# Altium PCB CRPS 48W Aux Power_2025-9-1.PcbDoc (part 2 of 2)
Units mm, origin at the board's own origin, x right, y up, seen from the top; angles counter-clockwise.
Board outline 50 x 33.8 mm, 6 copper layers (TopLayer, Layer2, Layer3, Layer4, Layer5, BottomLayer), stack 1.394 mm thick; 52 components, 33 nets, 144 pads, 115 vias.
Unrouted connection lines stored in the file: 30.
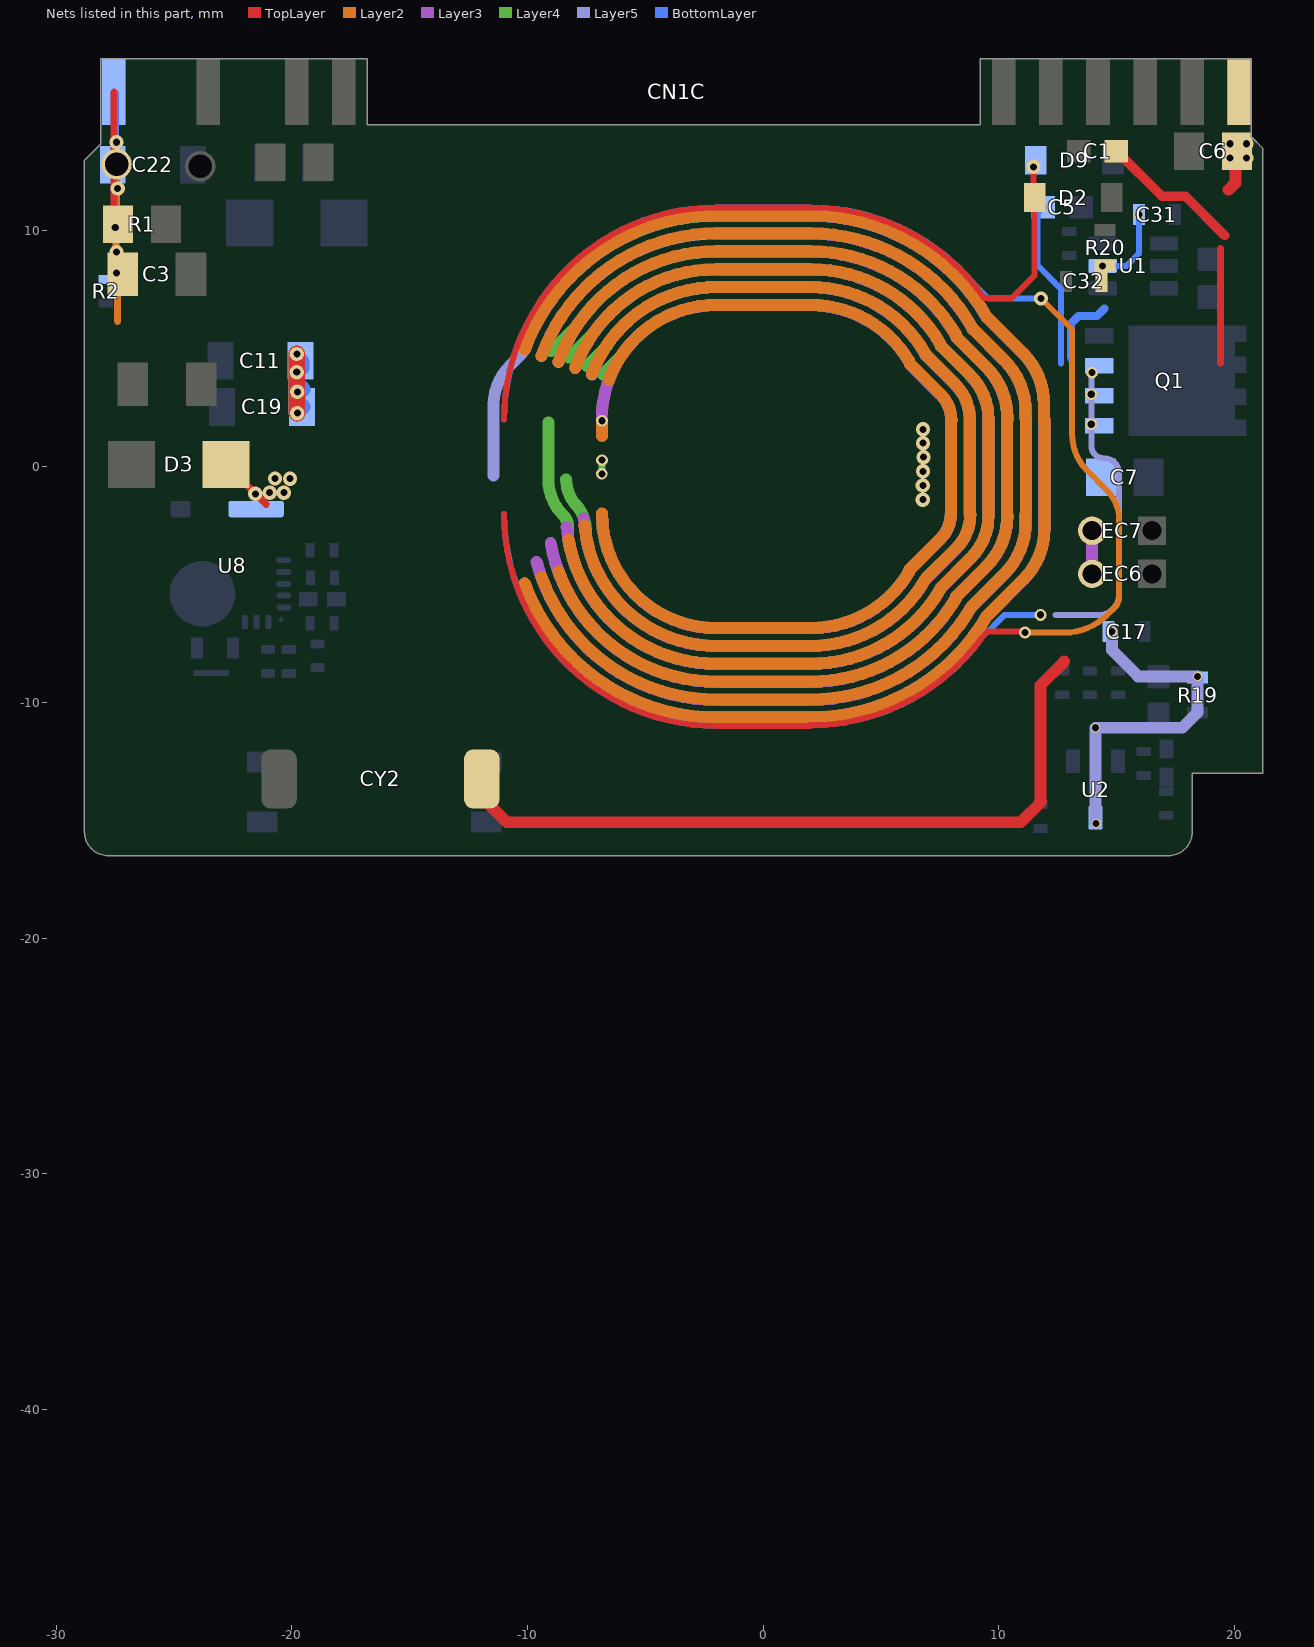
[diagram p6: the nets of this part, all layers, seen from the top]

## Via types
v1: diameter 0.61, hole 0.3, TopLayer to BottomLayer, tented both sides, 71 vias
v2: diameter 0.4, hole 0.3, TopLayer to BottomLayer, tented both sides, 19 vias
v3: diameter 0.5, hole 0.2, TopLayer to BottomLayer, tented both sides, 12 vias
v4: diameter 0.5, hole 0.3, Layer2 to Layer5, tented both sides, 8 vias
v5: diameter 0.508, hole 0.305, TopLayer to BottomLayer, 5 vias

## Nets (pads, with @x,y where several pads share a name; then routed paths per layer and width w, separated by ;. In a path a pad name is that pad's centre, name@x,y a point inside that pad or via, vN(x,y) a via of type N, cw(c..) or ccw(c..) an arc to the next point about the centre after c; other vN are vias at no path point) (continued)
SGND: C1.2 C6.2 C7.2 C17.1 CN1C.19 CN1C.20 CY2.1 EC6.2 EC7.2 R19.1 U2.3 | length 1205.6
  TopLayer w0.25: v1(20.5,13.096) v1(20.5,13.7)
  TopLayer w0.3: 19.396,4.395 19.396,9.246
  TopLayer w0.4: C1.2@14.984,13.377 15.009,13.377 16.914,11.472 17.91,11.472 19.572,9.809
  TopLayer w0.5: CY2.1@-11.942,-13.25 -12.261,-13.569 -12.261,-13.708 -10.881,-15.088 10.927,-15.088 11.762,-14.253 11.762,-9.274 12.764,-8.271
  TopLayer w0.505: 19.74,11.748 20.036,12.044 20.036,12.824 19.793,13.068 v1(19.793,13.096)
  Layer3 w0.5: 8.758,2.042 ccw(c8.786,2.042) 8.766,2.023
  Layer3 w0.505: -10.122,-4.958 ccw(c-1.996,-2) -1.996,-10.648 2.004,-10.648 ccw(c2.004,-2) 9.494,-6.324 ; -9.616,-4.042 ccw(c-1.996,-2) -1.996,-9.889 2.004,-9.889 ccw(c2.004,-2) 8.836,-5.944 ; -9.017,-3.238 ccw(c-1.996,-2) -1.996,-9.13 2.004,-9.13 ccw(c2.004,-2) 8.179,-5.565 ; -8.342,-2.555 ccw(c-1.996,-2) -1.996,-8.37 ; -7.603,-2.196 ccw(c-1.996,-2) -1.996,-7.611 ; -6.844,-2.004 ccw(c-1.996,-2.004) -1.996,-6.853 2.004,-6.853 ccw(c2.004,-2) 6.207,-4.426 ; -1.996,-8.371 2.004,-8.371 ; -1.996,-7.612 2.004,-7.612 ; -1.996,6.853 2.004,6.853 cw(c2.004,2) 6.207,4.427 ; -1.996,7.612 2.004,7.612 ; -1.996,8.371 2.004,8.371 ; -1.996,9.13 2.004,9.13 cw(c2.004,2) 8.179,5.565 ; -1.996,9.889 2.004,9.889 cw(c2.004,2) 8.836,5.945 ; -1.996,10.648 2.004,10.648 cw(c2.004,2) 9.494,6.324 ; 2.004,-8.37 ccw(c2.004,-2) 7.521,-5.185 ; 2.004,-7.611 ccw(c2.004,-2) 6.864,-4.805 ; 2.004,7.611 cw(c2.004,2) 6.864,4.806 ; 2.004,8.37 cw(c2.004,2) 7.521,5.185 ; 6.204,-4.375 7.53,-3.049 ccw(c6.506,-2.025) 7.954,-2.025 ; 6.229,4.35 7.52,3.06 cw(c6.41,1.95) 7.979,1.95 ; 6.879,-4.775 8.196,-3.458 ccw(c6.788,-2.05) 8.779,-2.05 ; 6.904,4.725 8.153,3.476 cw(c6.702,2.025) 8.754,2.025 ; 7.529,-5.15 8.812,-3.867 ccw(c7.019,-2.075) 9.554,-2.075 ; 7.529,5.125 8.776,3.878 cw(c6.899,2) 9.554,2 ; 7.969,-1.997 7.969,2.003 ; 8.179,-5.525 9.456,-4.248 ccw(c7.288,-2.08) 10.354,-2.08 10.354,-2.075 ; 8.204,5.475 9.456,4.223 cw(c7.288,2.055) 10.354,2.055 10.354,1.975 ; 8.761,-1.997 8.761,2.003 ; 8.854,-5.925 10.231,-4.548 ccw(c8.063,-2.38) 11.129,-2.38 11.129,-2.025 ; 8.879,5.85 10.231,4.498 cw(c8.063,2.33) 11.129,2.33 11.129,2.075 ; 9.525,6.299 11.006,4.818 cw(c8.838,2.65) 11.904,2.65 11.904,1.975 ; 9.529,-6.3 11.031,-4.798 ccw(c8.863,-2.63) 11.929,-2.63 11.929,2.003 ; 9.553,-1.997 9.553,2.003 ; 10.345,-1.997 10.345,2.003 ; 11.137,-1.997 11.137,2.003 ; EC6.2@13.95,-4.709 EC6.2@13.95,-4.548 EC7.2@13.95,-2.715 EC7.2@14.138,-2.715 ; v1@19.793,13.068 v1(19.793,13.7)
  Layer4 w0.3: v4(-6.849,-0.304) v4(-6.844,0.275)
  Layer4 w0.5: 8.754,2.042 ccw(c8.781,2.042) 8.762,2.023
  Layer4 w0.505: -10.126,-4.958 ccw(c-2,-2) -2,-10.648 2,-10.648 ccw(c2,-2) 9.489,-6.324 ; -9.12,1.868 -9.12,-0.543 ccw(c-6.989,-0.543) -8.496,-2.05 cw(c-9.034,-2.588) -8.273,-2.588 -8.273,-3.106 ccw(c-2,-2) -2,-8.37 ; -9.002,4.898 -7.85,6.05 ; -8.947,-3.604 ccw(c-2,-2) -2,-9.13 2,-9.13 ccw(c2,-2) 8.175,-5.565 ; -8.625,7.559 cw(c-2,2) -2,10.648 2,10.648 cw(c2,2) 9.489,6.324 ; -8.364,-0.531 ccw(c-6.727,-0.531) -7.993,-1.568 ccw(c-6.727,-0.531) -7.901,-1.672 cw(c-8.264,-2.023) -7.867,-1.71 cw(c-9.12,-2.696) -7.526,-2.696 -7.526,-2.974 ccw(c-2,-2) -2,-7.611 ; -8.252,4.623 -7.25,5.625 ; -7.841,6.09 cw(c-2,2) -2,9.13 2,9.13 cw(c2,2) 8.175,5.565 ; -7.477,4.273 -6.66,5.09 ccw(c-6.746,5.175) -6.625,5.175 ; -7.218,5.654 cw(c-2,2) -2,8.37 ; -6.853,-2 ccw(c-2,-2) -2,-6.853 2,-6.853 ccw(c2,-2) 6.203,-4.426 ; -6.812,3.913 -6.025,4.7 ; -6.596,5.218 cw(c-2,2) -2,7.611 ; -5.975,4.784 cw(c-2,2) -2,6.853 2,6.853 cw(c2,2) 6.203,4.427 ; -2,-8.371 2,-8.371 ; -2,-7.612 2,-7.612 ; -2,7.612 2,7.612 ; -2,8.371 2,8.371 ; 2,-8.37 ccw(c2,-2) 7.517,-5.185 ; 2,-7.611 ccw(c2,-2) 6.859,-4.805 ; 2,7.611 cw(c2,2) 6.859,4.806 ; 2,8.37 cw(c2,2) 7.517,5.185 ; 6.2,-4.375 7.526,-3.049 ccw(c6.501,-2.025) 7.95,-2.025 ; 6.225,4.35 7.515,3.06 cw(c6.406,1.95) 7.975,1.95 ; 6.875,-4.775 8.192,-3.458 ccw(c6.783,-2.05) 8.775,-2.05 ; 6.9,4.725 8.149,3.476 cw(c6.698,2.025) 8.75,2.025 ; 7.525,-5.15 8.808,-3.867 ccw(c7.015,-2.075) 9.55,-2.075 ; 7.525,5.125 8.772,3.878 cw(c6.894,2) 9.55,2 ; 7.965,-1.997 7.965,2.003 ; 8.175,-5.525 9.452,-4.248 ccw(c7.284,-2.08) 10.35,-2.08 10.35,-2.075 ; 8.2,5.475 9.452,4.223 cw(c7.284,2.055) 10.35,2.055 10.35,1.975 ; 8.757,-1.997 8.757,2.003 ; 9.52,6.299 11.002,4.818 cw(c8.834,2.65) 11.9,2.65 11.9,1.975 ; 9.525,-6.3 11.027,-4.798 ccw(c8.859,-2.63) 11.925,-2.63 11.925,2.003 ; 9.549,-1.997 9.549,2.003 ; 10.341,-1.997 10.341,2.003
  Layer2 w0.5: 8.763,2.056 ccw(c8.79,2.056) 8.771,2.037
  Layer2 w0.505: -10.118,-4.944 ccw(c-1.991,-1.986) -1.991,-10.634 2.009,-10.634 ccw(c2.009,-1.986) 9.498,-6.31 ; -10.118,4.972 cw(c-1.991,2.014) -1.991,10.662 2.009,10.662 cw(c2.009,2.014) 9.498,6.338 ; -9.405,-4.684 ccw(c-1.991,-1.986) -1.991,-9.875 2.009,-9.875 ccw(c2.009,-1.986) 8.841,-5.931 ; -9.405,4.712 cw(c-1.991,2.014) -1.991,9.903 2.009,9.903 cw(c2.009,2.014) 8.841,5.958 ; -8.691,-4.425 ccw(c-1.991,-1.986) -1.991,-9.116 2.009,-9.116 ccw(c2.009,-1.986) 8.183,-5.551 ; -8.691,4.452 cw(c-1.991,2.014) -1.991,9.144 2.009,9.144 cw(c2.009,2.014) 8.183,5.579 ; -8.265,-3.092 ccw(c-1.991,-1.986) -1.991,-8.356 ; -7.977,4.192 cw(c-1.991,2.014) -1.991,8.384 ; -7.581,-2.475 ccw(c-1.991,-1.986) -1.991,-7.597 2.009,-7.598 ccw(c2.009,-1.986) 6.868,-4.792 ; -7.264,3.933 cw(c-1.991,2.014) -1.991,7.625 ; -6.844,-1.986 ccw(c-1.991,-1.986) -1.991,-6.839 2.009,-6.839 ccw(c2.009,-1.986) 6.211,-4.413 ; -6.844,1.29 v4(-6.844,1.95) ; -6.552,3.674 cw(c-1.991,2.014) -1.991,6.867 2.009,6.867 cw(c2.009,2.014) 6.211,4.44 ; -1.991,-8.357 2.009,-8.357 ; -1.991,7.626 2.009,7.626 ; -1.991,8.385 2.009,8.385 ; 2.009,-8.356 ccw(c2.009,-1.986) 7.525,-5.171 ; 2.009,7.625 cw(c2.009,2.014) 6.868,4.819 ; 2.009,8.384 cw(c2.009,2.014) 7.525,5.199 ; 6.209,-4.361 7.534,-3.035 ccw(c6.51,-2.011) 7.959,-2.011 ; 6.234,4.364 7.524,3.073 cw(c6.414,1.964) 7.984,1.964 ; 6.884,-4.761 8.2,-3.445 ccw(c6.792,-2.036) 8.784,-2.036 ; 6.909,4.739 8.158,3.49 cw(c6.707,2.039) 8.759,2.039 ; 7.534,-5.136 8.816,-3.854 ccw(c7.024,-2.061) 9.559,-2.061 ; 7.534,5.139 8.781,3.892 cw(c6.903,2.014) 9.559,2.014 ; 7.974,-1.983 7.974,2.017 ; 8.184,-5.511 9.461,-4.234 ccw(c7.293,-2.066) 10.359,-2.066 10.359,-2.061 ; 8.209,5.489 9.461,4.237 cw(c7.293,2.069) 10.359,2.069 10.359,1.989 ; 8.766,-1.983 8.766,2.017 ; 8.859,-5.911 10.236,-4.534 ccw(c8.068,-2.366) 11.134,-2.366 11.134,-2.011 ; 8.884,5.864 10.236,4.512 cw(c8.068,2.344) 11.134,2.344 11.134,2.089 ; 9.529,6.313 11.011,4.832 cw(c8.843,2.664) 11.909,2.664 11.909,1.989 ; 9.534,-6.286 11.036,-4.784 ccw(c8.868,-2.616) 11.934,-2.616 11.934,2.017 ; 9.558,-1.983 9.558,2.017 ; 10.35,-1.983 10.35,2.017 ; 11.142,-1.983 11.142,2.017
  Layer5 w0.5: 8.763,2.042 ccw(c8.79,2.042) 8.771,2.023
  Layer5 w0.505: -11.445,-0.378 -11.445,0.203 -11.445,2.461 ccw(c-12.197,2.461) -11.45,2.553 cw(c-10.949,2.612) -11.454,2.625 cw(c-8.915,2.535) -10.711,4.331 -10.224,4.818 ; -10.118,-4.958 ccw(c-1.991,-2) -1.991,-10.648 2.009,-10.648 ccw(c2.009,-2) 9.498,-6.324 ; -10.118,4.958 cw(c-1.991,2) -1.991,10.648 2.009,10.648 cw(c2.009,2) 9.498,6.324 ; -9.405,-4.698 ccw(c-1.991,-2) -1.991,-9.889 2.009,-9.889 ccw(c2.009,-2) 8.841,-5.945 ; -9.405,4.698 cw(c-1.991,2) -1.991,9.889 2.009,9.889 cw(c2.009,2) 8.841,5.944 ; -8.81,-4.085 ccw(c-1.991,-2) -1.991,-9.13 2.009,-9.13 ccw(c2.009,-2) 8.183,-5.565 ; -8.691,4.439 cw(c-1.991,2) -1.991,9.13 2.009,9.13 cw(c2.009,2) 8.183,5.565 ; -8.265,-3.106 ccw(c-1.991,-2) -1.991,-8.37 ; -7.977,4.179 cw(c-1.991,2) -1.991,8.37 ; -7.581,-2.489 ccw(c-1.991,-2) -1.991,-7.611 ; -7.264,3.919 cw(c-1.991,2) -1.991,7.611 ; -6.844,-2 ccw(c-1.991,-2) -1.991,-6.853 2.009,-6.853 ccw(c2.009,-2) 6.211,-4.427 ; -6.552,3.66 cw(c-1.991,2) -1.991,6.853 2.009,6.853 cw(c2.009,2) 6.211,4.426 ; -1.991,-8.371 2.009,-8.371 ; -1.991,-7.612 2.009,-7.612 ; -1.991,7.612 2.009,7.612 ; -1.991,8.371 2.009,8.371 ; 2.009,-8.37 ccw(c2.009,-2) 7.525,-5.185 ; 2.009,-7.611 ccw(c2.009,-2) 6.868,-4.806 ; 2.009,7.611 cw(c2.009,2) 6.868,4.805 ; 2.009,8.37 cw(c2.009,2) 7.525,5.185 ; 6.209,-4.375 7.534,-3.049 ccw(c6.51,-2.025) 7.959,-2.025 ; 6.234,4.35 7.524,3.06 cw(c6.414,1.95) 7.984,1.95 ; 6.884,-4.775 8.2,-3.458 ccw(c6.792,-2.05) 8.784,-2.05 ; 6.909,4.725 8.158,3.476 ; 7.534,-5.15 8.816,-3.868 ccw(c7.024,-2.075) 9.559,-2.075 ; 7.534,5.125 8.781,3.878 cw(c6.903,2) 9.559,2 ; 7.974,-1.997 7.974,2.003 ; 8.158,3.476 cw(c6.706,2.025) 8.759,2.025 ; 8.184,-5.525 9.461,-4.248 ccw(c7.293,-2.08) 10.359,-2.08 10.359,-2.075 ; 8.209,5.475 9.461,4.223 cw(c7.293,2.055) 10.359,2.055 10.359,1.975 ; 8.766,-1.997 8.766,2.003 ; 8.859,-5.925 10.236,-4.548 ccw(c8.068,-2.38) 11.134,-2.38 11.134,-2.025 ; 8.884,5.85 10.236,4.498 cw(c8.068,2.33) 11.134,2.33 11.134,2.075 ; 9.529,6.299 11.011,4.818 cw(c8.843,2.65) 11.909,2.65 11.909,1.975 ; 9.534,-6.3 11.036,-4.798 ccw(c8.868,-2.63) 11.934,-2.63 11.934,2.003 ; 9.558,-1.997 9.558,2.003 ; 10.35,-1.997 10.35,2.003 ; 11.142,-1.997 11.142,2.003 ; v2(14.12,-15.139) 14.096,-15.115 v2(14.096,-11.075) 17.779,-11.075 18.428,-10.426 v2(18.428,-8.894) 15.904,-8.894 14.8,-7.79 v2(14.8,-7)
Vaux: D2.2 D9.2 | length 139.7
  TopLayer w0.25: v1(11.462,12.721) 11.462,11.472 D2.2@11.517,11.417
  TopLayer w0.254: -11,-2 ccw(c-2,-2) -2,-11 2,-11 ; -11,2 cw(c-2,2) -2,11 2,11 cw(c2,2) 9.372,7.162 10.558,7.162 11.517,8.121 D2.2@11.517,11.417 ; 2,-10.969 ccw(c2,-2) 9.26,-7.267 9.532,-6.995 11.057,-6.995 v5(11.1,-7.038)
  Layer2 w0.254: v5(11.1,-7.038) 12.783,-7.038 ccw(c12.783,-4.498) 14.579,-6.294 14.913,-5.96 ccw(c14.461,-5.508) 15.1,-5.508 15.1,-2.258 ccw(c13.321,-2.258) 14.579,-1 13.735,-0.156 cw(c15.27,1.378) 13.1,1.378 13.1,5.823 v1(11.786,7.137)
  BottomLayer w0.254: -10.996,-2 ccw(c-1.996,-2) -1.996,-11 2.004,-11 ; -10.996,2 cw(c-1.996,2) -1.996,11 2.004,11 cw(c2.004,2) 8.899,7.785 9.546,7.137 v1(11.786,7.137) ; 2.004,-10.969 ccw(c2.004,-2) 9.264,-7.267 ; 9.26,-7.267 10.244,-6.283 v5(11.762,-6.283)
Vbus: C3.2 C11.1 C19.1 C22.1 CN1C.2 pad.12@-27.439,12.833 R1.2 R2.2 | length 34.1
  TopLayer w0.305: pad.12@-27.55,12.75 v1@-27.55,11.8 ; -27.55,15.9 -27.55,13.763 -27.55,12.944 pad.12@-27.439,12.833 v1(-27.439,12.75) ; v1(-27.495,10.144) -27.495,10.232 -27.55,10.287 v1@-27.55,11.8 ; v1@-27.55,11.8 v1(-27.393,11.8) ; v1@-27.55,11.8 v1(-27.393,11.8) ; v1@-27.55,11.8 v1(-27.393,11.8) ; v1@-27.55,11.8 v1(-27.393,11.8) ; v1@-27.55,11.8 v1(-27.393,11.8) ; v1@-27.55,11.8 v1(-27.393,11.8) ; v1@-27.55,11.8 v1(-27.393,11.8) ; v1@-27.55,11.8 v1(-27.393,11.8)
  TopLayer w0.7: v1(-19.786,4.781) -19.786,2.284 v1(-19.77,2.269)
  Layer3 w0.505: -6.853,2 cw(c-2,2) -2,6.853
  Layer4 w0.7: v1(-19.786,4.781) -19.786,2.284 v1(-19.77,2.269)
  Layer2 w0.305: v1(-27.439,12.75) -27.439,11.8 -27.439,10.199 v1(-27.495,10.144) -27.467,10.116 -27.467,9.129 -27.444,9.105 -27.444,8.221 v1(-27.448,8.217) -27.402,8.17 -27.402,6.171
  Layer5 w0.7: v1(-19.786,4.781) -19.786,2.284 v1(-19.77,2.269)
  BottomLayer w0.305: CN1C.2@-27.55,15.9 -27.495,15.845 C22.1@-27.495,12.813
  BottomLayer w0.7: v1(-19.77,3.175) -19.77,3.096 -19.767,3.092 -19.767,2.735 C19.1@-19.567,2.535 ; C11.1@-19.636,4.496 -19.601,4.461 -19.601,4.204 v1(-19.793,4.013) -19.793,3.517 C19.1@-19.567,3.292
  other v1: -27.439,9.11 -27.439,13.763
VSR_SW: C5.2 C31.2 C32.2 Q1.1 Q1.2 Q1.3 R20.1 U1.2 | length 27.8
  TopLayer w0.254: C32.2@14.358,7.861 14.358,8.477 v2(14.4,8.52)
  Layer5 w0.254: 12.4,-6.3 14.216,-6.3 ccw(c14.216,-5.416) 15.1,-5.416 15.1,-0.292 ccw(c14.453,-0.292) 14.453,0.356 cw(c14.453,0.893) 13.916,0.893 v5(13.916,1.8) 13.933,1.817 v5@13.933,3.12 ; v5@13.916,3.102 v5@13.933,3.12 ; v5(13.95,4) 13.933,3.982 v5@13.933,3.12
  BottomLayer w0.25: Q1.1@13.887,1.771 v5(13.916,1.8)
  BottomLayer w0.254: C5.2@11.885,11 11.633,10.748 11.633,8.539 12.624,7.549 12.624,4.379 ; 13.056,4.518 13.056,4.648 ; v2(14.4,8.52) 15.413,8.52 15.938,9.044 v2(15.938,10.69)
  BottomLayer w0.35: 13.056,4.648 13.056,6.068 13.376,6.389 14.157,6.389 14.478,6.71
  other v1: 6.772,-1.4 6.772,-0.8 6.776,-0.2 6.799,0.406 6.776,1 6.776,1.581
  other v5: 13.916,3.073
VSW: D3.2 U8.2 | length 2.4
  TopLayer w0.305: D3.2@-22.8,0.1 -21.103,-1.597
  other v1: -21.55,-1.15 -20.944,-1.1 -20.339,-1.1 -20.716,-0.5 -20.079,-0.508
pads on no net: CN1C.1 CN1C.5 CN1C.6 CN1C.7 CN1C.8 CN1C.10 CN1C.11 CN1C.12 CN1C.13 CN1C.14 CN1C.15 CN1C.16 CN1C.18
copper on no net: | length 361.6
  TopLayer w0.254: -11,-2 -11,2
  TopLayer w0.305: 10.092,14.976 10.092,15.792 10.2,15.9 10.2,15.161 ; 17.85,15.434 17.97,15.554 18.2,15.9 ; 20.12,15.07 20.12,15.58 20.07,15.63 19.93,15.63 20.2,15.9 20.3,15.8 20.3,15.25
  Layer3 w0.5: -19.77,-0.722 -19.137,-0.722 ccw(c-19.137,0.432) -17.983,0.432 -17.983,1.219 cw(c-16.713,1.219) -16.713,2.489 ; -18.12,7.087 -18.12,6.298 ccw(c-18.086,6.298) -18.11,6.274 ccw(c-16.84,6.274) -16.84,5.004 -14.402,5.004 -13.722,5.004 cw(c-13.722,4.744) -13.538,4.928 cw(c-14.703,3.762) -13.056,3.762 v4(-13.056,1.4) ; -16.713,2.52 -15.128,2.52 -15.068,2.52 cw(c-15.068,1.651) -14.199,1.651 ccw(c-12.929,1.651) -12.929,0.381 -12.903,0.381 cw(c-12.903,-0.889) -11.633,-0.889 -11.633,-1.537 ; -11.633,-1.651 ccw(c-9.211,-1.651) -10.924,-3.364 -10.82,-3.467 cw(c-11.315,-3.962) -10.615,-3.962 ; -10.646,2.175 -10.646,-1.47 -10.646,-1.611 ccw(c-8.869,-1.611) -10.126,-2.868 cw(c-11.269,-4.011) -9.652,-4.011 ; -10.58,-4.011 -10.151,-4.934 ; -9.889,-0.859 -9.889,-1.172 ccw(c-8.429,-1.172) -9.461,-2.205 cw(c-10.457,-3.2) -9.049,-3.2 ; -9.889,-0.839 -9.889,2 ; -9.13,-0.722 -9.13,-0.204 -9.13,2 ; -9.105,-0.817 ccw(c-7.487,-0.817) -8.631,-1.961 cw(c-9.261,-2.591) -8.37,-2.591 ; -8.37,-0.445 -8.37,2 ; -8.338,-0.502 ccw(c-8.342,-0.506) -8.342,-0.5 ccw(c-6.957,-0.5) -7.936,-1.479 -7.878,-1.537 cw(c-8.523,-2.182) -7.611,-2.182 ; -7.625,-0.121 -7.625,1.966 cw(c-7.577,1.966) -7.611,2 ; -7.611,-0.204 ccw(c-6.426,-0.204) -7.264,-1.042 -7.176,-1.13 cw(c-7.939,-1.893) -6.86,-1.893
  Layer3 w0.505: -10.648,2 cw(c-2,2) -2,10.648 ; -9.889,2 cw(c-2,2) -2,9.889 ; -9.13,2 cw(c-2,2) -2,9.13 ; -8.37,2 cw(c-2,2) -2,8.37 ; -7.611,2 cw(c-2,2) -2,7.611 ; v4@-6.85,1.325 -6.85,2.175
  Layer4 w0.5: -19.66,8.575 -19.66,7.73 ccw(c-18.966,7.73) -19.456,7.239 cw(c-20.315,6.381) -19.101,6.381 -19.101,6.192 ; -19.101,6.092 ccw(c-19.099,6.092) -19.099,6.09 cw(c-19.099,6.091) -19.1,6.091 ; -19.1,6.141 ccw(c-18.076,6.141) -18.8,5.416 ccw(c-17.795,6.421) -17.795,5 -17.6,5 -11.6,5 ccw(c-11.6,6.005) -10.889,5.294 -8.625,7.559 ; -14.275,0.508 cw(c-13.232,1.55) -14.707,1.55 -14.707,2.068 cw(c-12.799,2.068) -14.148,3.418 -14.114,3.451 cw(c-12.573,1.91) -12.573,4.089 ; -14.251,0.484 -14.03,0.263 ccw(c-12.257,2.036) -12.257,-0.471 cw(c-12.257,-1.03) -11.862,-0.635 cw(c-12.494,-1.267) -11.6,-1.267 -11.6,-1.455 ; -13.818,1.067 cw(c-13.388,1.496) -13.995,1.496 -13.995,2.109 cw(c-12.955,2.109) -13.691,2.845 cw(c-12.336,1.491) -12.336,3.406 -11.19,3.569 ; -13.792,1.041 ccw(c-11.942,2.892) -11.942,0.275 -11.776,0.275 cw(c-11.776,-0.501) -11.228,0.048 -11.1,-0.08 cw(c-12.081,-1.061) -10.693,-1.061 -10.693,-1.455 ccw(c-8.836,-1.455) -10.149,-2.769 ; v4@-13.056,1.393 ccw(c-12.207,2.242) -12.207,1.041 -11.776,1.041 cw(c-11.776,-0.654) -10.578,0.545 cw(c-12.023,-0.9) -9.979,-0.9 ccw(c-8.023,-0.9) -9.406,-2.284 -9.277,-2.413 cw(c-9.941,-3.077) -9.002,-3.077 -9.002,-3.477 ; v4(-13.056,1.4) v4(-13.056,1.953) ; -12.522,4.089 -11.462,4.273 ccw(c-11.462,6.13) -10.149,4.817 ; v4@-12.197,2.33 v4(-12.197,1.939) ; v4(-12.197,2.461) v4(-12.197,1.939) ; -11.6,-1.513 ccw(c-9.285,-1.513) -10.922,-3.15 ; -11.151,3.569 ccw(c-11.151,5.607) -9.709,4.166 -9.593,4.283 ; -10.889,-3.175 -10.167,-4.899 ; -10.176,4.79 -10.149,4.817 ; -10.094,-2.828 cw(c-10.999,-3.734) -9.719,-3.734 -9.509,-4.407 ; -9.841,5.125 -10.149,4.817 ; -9.565,4.336 -9.002,4.898 ; -9.519,3.345 cw(c-10.848,4.674) -10.848,2.794 -11.339,2.794 ccw(c-11.339,1.58) -12.197,2.438 v4(-12.197,1.939) ; -9.509,3.366 -9.516,3.359 -9.351,3.524 -9.277,3.598 -8.252,4.623 ; -9.116,1.939 cw(c-7.438,1.939) -8.625,3.125 -7.477,4.273 ; -8.973,-3.541 cw(c-9.036,-3.604) -8.947,-3.604 ; -8.364,-0.531 ccw(c-8.372,-0.523) -8.36,-0.523 -8.36,2.134 cw(c-7.803,2.134) -8.197,2.528 -6.812,3.913 ; -7.29,1.4 -6.877,1.95 -6.883,1.956 ; -6.86,-1.893 cw(c-6.877,-1.91) -6.853,-1.91 -6.853,-2 ccw(c-7.685,-2) -7.097,-1.412 -7.352,-1.156 cw(c-6.727,-0.531) -7.611,-0.531 -7.611,0.1 -7.611,0.753 cw(c-7.022,0.753) -7.438,1.169 cw(c-7.147,0.878) -7.147,1.29 v4(-6.844,1.29) -6.844,1.95
  Layer4 w0.505: -9.752,5.223 -8.5,6.475 ; -9.503,-4.438 ccw(c-2,-2) -2,-9.889 2,-9.889 ccw(c2,-2) 8.832,-5.945 ; -8.462,6.525 cw(c-2,2) -2,9.889 2,9.889 cw(c2,2) 8.832,5.944 ; 8.85,-5.925 10.227,-4.548 ccw(c8.059,-2.38) 11.125,-2.38 ; 8.875,5.85 10.227,4.498 cw(c8.059,2.33) 11.125,2.33 ; 11.133,-2.38 11.133,2.203
  Layer2 w0.5: -18.974,3.378 -18.059,3.378 ; -18.194,3.378 -12.548,3.378 ccw(c-12.548,5.5) -11.047,4 -10.148,4.899 ; v4(-13.056,1.4) v4(-13.056,1.953) ; v4(-12.197,1.939) v4(-12.197,2.461) ; -10.151,-4.934 cw(c-9.42,-4.204) -10.453,-4.204 -10.453,2.394 cw(c-7.387,2.394) -9.555,4.562 -9.405,4.712 ; -9.405,-4.684 cw(c-8.646,-3.926) -9.719,-3.926 -9.719,2.409 cw(c-7.431,2.409) -9.049,4.026 -8.74,4.335 ccw(c-8.858,4.452) -8.691,4.452 ; -8.966,-3.752 -8.966,2.359 cw(c-7.227,2.359) -8.457,3.588 -8.001,4.115 ; -8.941,-3.81 -8.937,-3.817 -8.712,-4.318 ; -8.719,-4.361 -8.713,-4.368 ; -8.273,-3.106 -8.273,1.917 cw(c-5.91,1.917) -7.581,3.588 -7.283,3.886 ccw(c-7.33,3.933) -7.264,3.933 ; -7.585,-2.489 -7.585,1.924 cw(c-5.977,1.924) -7.114,3.061 -6.587,3.588 ccw(c-6.672,3.674) -6.552,3.674 ; -6.86,-1.893 ccw(c-6.882,-1.871) -6.851,-1.871 -6.851,0.2 ; -6.851,-0.293 -6.851,0.273 cw(c-6.844,0.273) -6.849,0.278 cw(c-6.834,0.278) -6.844,0.289 ; -6.847,-0.288 ccw(c-6.852,-0.283) -6.844,-0.283 -6.844,0.142 ; -6.844,-1.991 -6.844,-1.838 ; 6.772,-1.4 ccw(c6.742,-1.37) 6.785,-1.37
  Layer5 w0.254: 11.762,-6.283 11.779,-6.3 12.4,-6.3
  Layer5 w0.5: v4(-13.056,1.4) v4(-13.056,1.953) ; v4@-12.197,2.136 v4(-12.197,2.461) ; v4@-12.197,2.298 -12.197,-1.617 ccw(c-9.131,-1.617) -11.299,-3.785 -10.151,-4.934 ; -11.445,-0.378 -11.445,-1.307 ccw(c-8.379,-1.307) -10.547,-3.475 -10.475,-3.547 ccw(c-10.431,-3.504) -10.431,-3.565 ; -10.65,0.7 -10.65,-0.894 ccw(c-7.584,-0.894) -9.752,-3.062 -8.893,-3.922 cw(c-9.216,-4.245) -8.759,-4.245 ; -10.646,0.283 -10.646,2.031 ; -10.647,2.136 cw(c-7.837,2.136) -9.824,4.123 -9.459,4.57 -9.449,4.572 ; -10.402,-3.594 -9.475,-4.521 ; -10.175,-4.91 -10.126,-4.958 ; -9.48,-4.516 cw(c-9.662,-4.698) -9.405,-4.698 ; -9.12,0.285 -9.12,2.036 ; -9.12,0.416 ccw(c-9.097,0.393) -9.13,0.393 -9.13,-0.463 ccw(c-7.967,-0.463) -8.789,-1.285 -7.585,-2.489 ; -9.112,2.055 cw(c-7.375,2.055) -8.603,3.284 -8.168,3.719 ccw(c-8.499,4.05) -8.031,4.05 ; -9.042,3.833 -8.755,4.283 -8.763,4.293 ; -9.041,3.834 ccw(c-6.994,1.787) -9.889,1.787 -9.889,0.417 -9.889,-0.445 ccw(c-7.366,-0.445) -9.15,-2.229 -8.273,-3.106 ; -7.625,1.876 cw(c-6.625,1.876) -7.332,2.584 -6.761,3.155 ccw(c-7.265,3.66) -6.552,3.66 ; -7.619,1.99 -7.619,1.078 ccw(c-7.036,1.078) -7.448,0.666 -7.177,0.395 ccw(c-6.851,0.721) -6.851,0.26 ; -7.264,3.919 cw(c-7.892,3.919) -7.448,3.475 -8.066,2.857 ccw(c-7.357,2.148) -8.36,2.148 -8.36,1.03 ccw(c-8.336,1.006) -8.37,1.006 -8.37,0 ccw(c-7.394,0) -8.084,-0.69 -6.853,-1.921 ; -6.847,-0.302 ccw(c-6.852,-0.297) -6.844,-0.297 -6.844,0.129 ; -6.844,0.275 ccw(c-6.834,0.265) -6.849,0.265 ccw(c-6.844,0.259) -6.851,0.259 ; -6.851,0.26 -6.851,-0.306 -6.851,0.259
  Layer5 w0.505: -6.85,1.865 v4(-6.844,1.29)
  BottomLayer w0.254: -10.996,-2 -10.996,2
  BottomLayer w0.305: 10.108,15.292 10.239,15.423 10.239,15.861 10.2,15.9 ; 12.2,15.9 12.27,15.83 12.27,14.62 ; 17.434,-47.143 17.473,-47.182 17.473,-47.62

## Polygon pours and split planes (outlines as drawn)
SGND on TopLayer "SGND_L01_P025" (solid, remove dead copper, pour order 25): 18.844,6.607 18.078,5.841 15.85,5.843 15.325,5.317 15.325,1.173 14.416,0.518 12.522,0.496 12.522,-1.93 15.07,-1.93 15.07,-0.446 15.592,0.076 20.676,0.076 21,0.401 21,14.453 20.873,14.58 19.409,14.58 18.849,14.02
+12V on TopLayer "+12V_L01_P008" (solid, remove dead copper, pour order 8): 15.4,-0.33 15.4,-9.936 20.92,-9.936 20.925,-0.732 20.523,-0.33
SGND on TopLayer "SGND_L01_P007" (solid, remove dead copper, pour order 7): 12.497,0.25 12.497,-10.008 15.1,-10.008 15.1,0.076 14.927,0.25
PGND on TopLayer "PGND_L01_P037" (solid, remove dead copper, pour order 37): -25.248,14.931 -25.248,11.823 -23.926,11.823 -22.247,10.144 -18.71,10.144 -17.828,11.026 -17.828,13.383 -18.694,14.249 -22.149,14.249 -22.831,14.931 -25.197,14.931
+12V on TopLayer "PGND" (solid, remove dead copper, pour order 6): 18.801,14.577 17.406,14.584 17.09,14.184 17.09,12.294 18.999,12.294 18.999,14.351
SGND on TopLayer "PGND" (solid, remove dead copper, pour order 5): 19.711,14.902 19.711,12.796 20.7,12.796 20.7,14.902
Vbus on TopLayer "PGND" (solid, remove dead copper, pour order 3): -28.388,15.431 -28.388,7.087 -26.508,7.087 -26.508,15.431
VSR_SW on TopLayer "VSR_SW_L01_P001" (solid, remove dead copper, pour order 1): -10.693,8.848 -10.693,-7.872 -6.96,-11.605 6.424,-11.605 8.668,-7.445 10.263,-5.7 12.2,-5.669 12.2,4.521 9.971,6.75 4.295,12.427 -7.114,12.427
PGND on TopLayer "PGND" (solid, remove dead copper, pour order 0): -25.248,14.931 -25.248,11.836 -23,11.836 -23,14.931
PGND on TopLayer "PGND_L01_P022" (solid, remove dead copper, pour order 22): -28.169,-2.835 -19.6,-2.835 -19.6,-15.926 -28.281,-15.926 -28.281,-2.835
SGND on TopLayer "SGND_L01_P047" (solid, remove dead copper, pour order 47): 20.873,-10.425 20.873,-12.653 18.194,-12.653 17.74,-13.107 17.74,-15.96 17.393,-16.307 12.522,-16.307 12.522,-10.45 12.497,-10.425
VSR_SW on TopLayer "VSR_SW_L01_P026" (solid, remove dead copper, pour order 26): 12.421,10.909 12.421,6.462 12.711,6.172 17.92,6.172 18.5,6.752 18.5,9.677 17.269,10.909
NetC3_1 on TopLayer "NETC3_1_L01_P013" (solid, remove dead copper, pour order 13): -26.025,11.11 -26.025,9.21 -24.968,8.153 -24.968,2.184 -22.923,2.184 -22.923,8.331 -24.394,9.803 -24.394,11.11
VSW on TopLayer "VSW_L01_P014" (solid, remove dead copper, pour order 14): -23.775,1.1 -23.775,-0.526 -22.548,-1.753 -19.738,-1.753 -19.6,-1.615 -19.6,-0.103 -21.512,-0.103 -21.758,0.143 -21.758,1.1
NetD3_1 on TopLayer "NETD3_1_L01_P012" (solid, remove dead copper, pour order 12): -28.388,5.162 -28.388,-0.312 -27.8,-0.9 -25.8,-0.9 -25.8,1.1 -25.8,5.162
SGND on BottomLayer "SGND_L06_P046" (solid, remove dead copper, pour order 46): 19.507,14.783 19.507,12.6 20.92,12.6 20.92,14.8 20.902,14.783 19.533,14.783
Vbus on BottomLayer "VBUS_L06_P016" (solid, remove dead copper, pour order 16): -28.388,15.431 -28.388,7.518 -26.35,7.518 -26.35,15.431
PGND on BottomLayer "PGND_L06_P019" (solid, remove dead copper, pour order 19): -22.4,6.031 -22.409,6.04 -22.409,8.435 -23.325,9.35 -23.325,11.982 -22.997,12.31 -22.997,13.167 -23.851,14.021 -24.889,14.021 -25.364,13.546 -25.364,6.031 -25.835,5.55 -28.281,5.551 -28.281,-15.926 -19.77,-15.926 -19.77,-3.111 -19.961,-2.921 -26.264,-2.921 -26.264,-0.635 -25.394,-0.635 -25.394,-0.045 -23.901,1.448 -22.4,1.448
NetR2_1 on BottomLayer "NETR2_1_L06_P059" (solid, remove dead copper, pour order 59): -25.494,-1.386 -24.395,-1.386 -24.282,-1.499 -24.282,-2.097 -24.344,-2.159 -25.527,-2.159 -25.709,-1.977 -25.709,-1.601
+12V on BottomLayer "+12V_L06_P056" (solid, remove dead copper, pour order 56): 16.907,12.294 19.09,12.294 19.09,14.083 16.89,14.083 16.907,14.066 16.907,12.696
VSR_SW on BottomLayer "VSR_SW_L06_P023" (solid, remove dead copper, pour order 23): 11.227,4.75 14.82,4.75 15.113,4.457 15.113,1.393 14.863,1.143 13.144,1.143 12.894,1.393 11.227,1.393
Vbus on BottomLayer "VBUS_L06_P021" (solid, remove dead copper, pour order 21): -20.269,5.269 -20.269,1.549 -18.912,1.549 -18.912,5.303 -20.244,5.303 -20.244,5.309
APGND on BottomLayer "APGND_L06_P002" (solid, remove dead copper, pour order 2): -18.491,-3.2 -18.491,-8.687 -18.72,-8.915 -19.282,-8.915 -19.739,-8.458 -23.462,-8.458 -23.462,-9.311 -18.25,-9.305 -17.907,-8.915 -17.907,-3.277 -17.983,-3.2
VSW on BottomLayer "VSW_L06_P020" (solid, remove dead copper, pour order 20): -22.553,-0.111 -19.962,-0.111 -19.753,-0.32 -19.753,-1.98 -19.907,-2.134 -22.678,-2.134 -22.678,-0.183
+12V on BottomLayer "+12V_L06_P011" (solid, remove dead copper, pour order 11): 15.544,6.03 15.544,-7.569 21,-7.569 21,6.03
VSR_SW on BottomLayer "VSR_SW_L06_P015" (solid, remove dead copper, pour order 15): 13.264,6.529 19.406,6.529 19.406,11.271 18.679,11.997 13.264,11.997
SGND on BottomLayer "SGND_L06_P010" (solid, remove dead copper, pour order 10): 12.518,0.648 12.518,-7.601 15.256,-7.601 15.256,0.648
VSR_SW on BottomLayer "VSR_SW_L06_P009" (solid, pour order 9): -10.611,8.948 -10.611,-7.937 -6.96,-11.588 4.712,-11.588 9.971,-6.329 12.177,-4.283 12.177,3.34 11.771,4.556 10.865,5.463 9.971,6.356 3.883,12.444 -7.114,12.444
SGND on Layer2 "SGND_L02_P053" (solid, remove dead copper, pour order 53): 20.809,-10.425 20.809,-12.728 18.049,-12.771 17.677,-13.107 17.677,-15.96 17.329,-16.307 12.458,-16.307 12.458,-10.45 12.433,-10.425
VSR_SW on Layer2 "VSR_SW_L02_P018" (solid, remove dead copper, pour order 18): 12.421,10.31 12.421,6.435 12.711,6.145 17.92,6.145 18.5,6.725 18.5,9.819 18.009,10.31
+12V on Layer2 "+12V_L02_P049" (solid, remove dead copper, pour order 49): 15.499,14.199 15.499,-9.855 20.955,-9.855 20.955,14.199
PGND on Layer2 "PGND_L02_P044" (solid, remove dead copper, pour order 44): -25.15,14.738 -25.15,7.056 -24.394,6.3 -18.186,6.3 -17.526,6.96 -17.526,14.732
PGND on Layer2 "PGND_L02_P038" (solid, remove dead copper, pour order 38): -28.194,-2.859 -19.625,-2.859 -19.625,-15.95 -28.306,-15.95 -28.306,-2.859
Vbus on Layer2 "VBUS_L02_P028" (solid, pour order 28): -28.448,15.6 -28.448,3.44 -26.608,1.6 -18.72,1.6 -18.72,5.089 -25.544,5.089 -26.1,5.578 -26.1,15.1 -26.6,15.6
+12V on Layer3 "+12V_L03_P058" (solid, remove dead copper, pour order 58): 16.862,12.319 19.045,12.319 19.045,14.108 16.845,14.108 16.862,14.091 16.862,12.721
SGND on Layer3 "SGND_L03_P050" (solid, remove dead copper, pour order 50): 19.253,14.453 19.253,12.267 18.714,11.728 18.729,9.855 16.434,9.855 16.434,0.61 16.099,0.275 13.542,0.275 12.979,-0.287 12.979,-9.423 21.031,-9.423 21.031,14.453
SGND on Layer3 "SGND_L03_P054" (solid, remove dead copper, pour order 54): 21,-10.425 21,-12.726 18.049,-12.771 17.677,-13.107 17.677,-15.96 17.329,-16.307 12.433,-16.307 12.433,-10.425
VSR_SW on Layer3 "VSR_SW_L03_P027" (solid, remove dead copper, pour order 27): 12.344,10.295 12.344,6.478 12.693,6.13 17.902,6.13 18.482,6.71 18.482,9.804 17.991,10.295
PGND on Layer3 "PGND_L03_P045" (solid, remove dead copper, pour order 45): -25.15,14.738 -25.15,9.11 -17.526,9.11 -17.526,14.732
PGND on Layer3 "PGND_L03_P039" (solid, remove dead copper, pour order 39): -28.194,-2.859 -19.625,-2.859 -19.625,-15.95 -28.306,-15.95 -28.306,-2.859
Vbus on Layer3 "VBUS_L03_P029" (solid, pour order 29): -28.531,15.673 -28.531,3.513 -26.692,1.673 -18.803,1.673 -18.803,5.162 -22.366,5.162 -26.183,8.516 -26.183,15.173 -26.683,15.673
VSR_SW on Layer5 "VSR_SW_L05_P031" (solid, remove dead copper, pour order 31): 12.403,11.201 12.403,6.42 12.693,6.13 17.902,6.13 18.482,6.71 18.482,9.804 17.085,11.201
+12V on Layer5 "+12V_L05_P052" (solid, remove dead copper, pour order 52): 15.499,14.199 15.499,-7.465 20.955,-7.465 20.955,14.199
PGND on Layer5 "PGND_L05_P042" (solid, remove dead copper, pour order 42): -25.397,14.788 -25.397,7.381 -24.366,6.35 -18.157,6.35 -17.498,7.01 -17.498,14.782
Vbus on Layer5 "VBUS_L05_P041" (solid, remove dead copper, pour order 41): -28.3,15.441 -28.3,6.941 -28.262,6.904 -26.508,6.904 -26.508,15.472 -28.388,15.472
PGND on Layer5 "PGND_L05_P036" (solid, remove dead copper, pour order 36): -28.281,5.788 -22.4,5.788 -22.4,1.586 -23.763,1.586 -25.394,-0.045 -25.394,-2.921 -19.961,-2.921 -19.77,-3.111 -19.77,-15.926 -28.281,-15.926
PGND on Layer5 "PGND_L05_P032" (solid, remove dead copper, pour order 32): -25.5,14 -25.5,2.302 -22.377,2.302 -22.377,14
+12V on Layer4 "+12V_L04_P057" (solid, remove dead copper, pour order 57): 16.879,12.231 19.062,12.231 19.062,14.021 16.862,14.021 16.879,14.004 16.879,12.634
SGND on Layer4 "SGND_L04_P055" (solid, remove dead copper, pour order 55): 21.002,-10.425 21.002,-12.726 18.051,-12.771 17.679,-13.107 17.679,-15.96 17.332,-16.307 12.435,-16.307 12.435,-10.425
VSR_SW on Layer4 "VSR_SW_L04_P033" (solid, remove dead copper, pour order 33): 12.403,10.295 12.403,6.42 12.693,6.13 17.902,6.13 18.482,6.71 18.482,9.804 17.991,10.295
SGND on Layer4 "SGND_L04_P051" (solid, remove dead copper, pour order 51): 19.239,14.453 19.267,10.381 16.434,7.548 16.434,0.61 16.099,0.275 13.542,0.275 12.878,-0.389 12.878,-9.691 21.031,-9.691 21.031,14.453
PGND on Layer4 "PGND_L04_P048" (solid, remove dead copper, pour order 48): -25.425,14.738 -25.425,7.331 -24.394,6.3 -18.186,6.3 -17.526,6.96 -17.526,14.732
Vbus on Layer4 "VBUS_L04_P040" (solid, remove dead copper, pour order 40): -28.3,15.441 -28.3,6.941 -28.262,6.904 -26.508,6.904 -26.508,15.472 -28.388,15.472
PGND on Layer4 "PGND_L04_P035" (solid, remove dead copper, pour order 35): -28.281,5.788 -22.4,5.788 -22.4,1.586 -23.763,1.586 -25.394,-0.045 -25.394,-2.921 -19.961,-2.921 -19.77,-3.111 -19.77,-15.926 -28.281,-15.926
PGND on Layer4 "PGND_L04_P034" (solid, remove dead copper, pour order 34): -25.5,14 -25.5,2.302 -22.4,2.302 -22.4,14

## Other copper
TopLayer:
  pour cut-out: 6.325,-1.93 6.325,-2.355 12.319,-2.355 12.319,-1.93
Layer3:
  rectangle net VSR_SW: 6.452,-1.727 7.121,1.901
  rectangle net VSW: -22.006,-1.645 -19.282,-0.103
Layer4:
  rectangle net VSW: -22.029,-1.622 -19.305,-0.08
  rectangle net VSR_SW: 6.458,-1.727 7.128,1.901
Layer2:
  rectangle net Vbus: -20.245,1.7 -18.7,3.505
  rectangle net VSW: -22.006,-1.645 -19.282,-0.103
  rectangle net VSR_SW: 6.443,-1.753 7.112,1.875
  rectangle net Vbus: -20.079,2.235 -18.72,4.452
Layer5:
  rectangle net VSW: -22.006,-1.645 -19.282,-0.103
  rectangle net VSR_SW: 6.452,-1.727 7.121,1.901
BottomLayer:
  pour cut-out: 8.063,1.393 7.408,2.424 6.31,2.409 6.325,1.93 7.29,1.93 7.874,0.933 12.2,0.933 12.2,1.393

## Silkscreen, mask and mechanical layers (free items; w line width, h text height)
Silkscreen Bottom:
  text "PMP41184" at -2.13,-14.747 h1.52 r180
Solder Mask Top:
  region: 12.169,-5.385 12.169,-2.667 10.319,-2.667 10.319,-5.385
  rectangle: 12.711,-7.341 15.037,-2
  rectangle: 73.2,5 75.2,7
  rectangle: 73.2,-12.5 75.2,-10.5
  rectangle: 73.2,23.3 75.2,25.3
  rectangle: 73.2,40.8 75.2,42.8
  rectangle: 21.2,40.8 23.2,42.8
  rectangle: 21.2,23.3 23.2,25.3
  rectangle: -30.8,23.3 -28.8,25.3
  rectangle: -30.8,40.8 -28.8,42.8
  rectangle: 73.2,59.1 75.2,61.1
  rectangle: 73.2,76.6 75.2,78.6
  rectangle: 21.2,76.6 23.2,78.6
  rectangle: 21.2,59.1 23.2,61.1
  rectangle: -30.8,59.1 -28.8,61.1
  rectangle: -30.8,76.6 -28.8,78.6
  rectangle: 73.2,94.9 75.2,96.9
  rectangle: 73.2,112.4 75.2,114.4
  rectangle: 21.2,112.4 23.2,114.4
  rectangle: 21.2,94.9 23.2,96.9
  rectangle: -30.8,94.9 -28.8,96.9
  rectangle: -30.8,112.4 -28.8,114.4
  rectangle: 73.2,130.7 75.2,132.7
  rectangle: 73.2,148.2 75.2,150.2
  rectangle: 21.2,148.2 23.2,150.2
  rectangle: 21.2,130.7 23.2,132.7
  rectangle: -30.8,130.7 -28.8,132.7
  rectangle: -30.8,148.2 -28.8,150.2
Solder Mask Bottom:
  region: 15.156,-6.396 15.156,0.442 12.686,0.442 12.686,-6.396
  region: 20.808,-5.41 20.808,6.065 15.443,6.065 15.443,-5.41
  rectangle: 9.601,1.372 14.988,4.623
  rectangle: -30.8,148.2 -28.8,150.2
  rectangle: -30.8,130.7 -28.8,132.7
  rectangle: 21.2,130.7 23.2,132.7
  rectangle: 21.2,148.2 23.2,150.2
  rectangle: 73.2,148.2 75.2,150.2
  rectangle: 73.2,130.7 75.2,132.7
  rectangle: -30.8,112.4 -28.8,114.4
  rectangle: -30.8,94.9 -28.8,96.9
  rectangle: 21.2,94.9 23.2,96.9
  rectangle: 21.2,112.4 23.2,114.4
  rectangle: 73.2,112.4 75.2,114.4
  rectangle: 73.2,94.9 75.2,96.9
  rectangle: -30.8,76.6 -28.8,78.6
  rectangle: -30.8,59.1 -28.8,61.1
  rectangle: 21.2,59.1 23.2,61.1
  rectangle: 21.2,76.6 23.2,78.6
  rectangle: 73.2,76.6 75.2,78.6
  rectangle: 73.2,59.1 75.2,61.1
  rectangle: -30.8,40.8 -28.8,42.8
  rectangle: -30.8,23.3 -28.8,25.3
  rectangle: 21.2,23.3 23.2,25.3
  rectangle: 21.2,40.8 23.2,42.8
  rectangle: 73.2,40.8 75.2,42.8
  rectangle: 73.2,23.3 75.2,25.3
  rectangle: 73.2,-12.5 75.2,-10.5
  rectangle: 73.2,5 75.2,7
  rectangle: 21.2,5 23.2,7
  rectangle: 21.2,-12.5 23.2,-10.5
  rectangle: -30.8,-12.5 -28.8,-10.5
  rectangle: -30.8,5 -28.8,7
Mechanical1:
  drawing of 522 lines, arcs and shapes, not listed
  text "所有工艺边请铺铜距板边沿0.5mm以上" at -24.61,164.575 h1.5
  text "所有工艺边请铺铜距板边沿0.5mm以上" at 48.85,163.896 h1.5
  text "SLOT" at 22.8,157.4 h0.75 r90
  text "SLOT" at 74.6,157.1 h0.75 r90
  text "SLOT" at -28.959,156.726 h0.75 r90
  text "SLOT" at 74.586,139.759 h0.6 r90
  text "SLOT" at -29.427,139.251 h0.6 r90
  text "SLOT" at 22.389,138.743 h0.6 r90
  text "SLOT" at 21.089,125.563 h0.6
  text "SLOT" at 74.586,103.959 h0.6 r90
  text "SLOT" at -29.427,103.451 h0.6 r90
  text "SLOT" at 22.389,102.943 h0.6 r90
  text "SLOT" at 21.089,89.763 h0.6
  text "所有实体连接位请不要铺铜" at -5.713,79.061 h1.5
  text "所有实体连接位请不要铺铜" at -56.688,78.928 h1.5
  text "SLOT" at 74.586,68.159 h0.6 r90
  text "SLOT" at -29.427,67.651 h0.6 r90
  text "SLOT" at 22.389,67.143 h0.6 r90
  text "所有实体连接位请不要铺铜" at -5.587,61.574 h1.5
  text "所有实体连接位请不要铺铜" at -56.914,61.304 h1.5
  text "SLOT" at 21.089,53.963 h0.6
  text "2.00mm" at 61.026,53.868 h0.5
  text "4.80mm" at 47.696,52.515 h0.5
  text "2.80mm" at 35.77,51.378 h0.5
  text "177.00mm" at -43.175,51.009 h0.5
  text "2" at -44.453,50.976 h0.75
  text "2.50mm" at 68.481,50.41 h0.5
  text "16.30mm" at 76.174,48.371 h0.5
  text "2.00mm" at 67.913,41.689 h0.5
  text "2.00mm" at 75.764,35.24 h0.5
  text "SLOT" at 22.643,32.881 h0.6 r90
  text "15.50mm" at 69.321,32.673 h0.5
  text "SLOT" at 74.586,32.359 h0.6 r90
  text "SLOT" at -29.427,31.851 h0.6 r90
  text "2.00mm" at 75.486,24.089 h0.5
  text "6.00mm" at 69.515,21.924 h0.5
  text "0.5粗线侧壁镀铜,其它侧不允许残铜" at -59.906,20.587 h1.5
  text "SLOT" at 20.095,19.822 h0.6
  text "0.5粗线侧壁镀铜,其它侧不允许残铜" at 23.524,18.044 h1.5
  text "两条边不允许露铜，所有焊盘上侧正反面削铜0.3mm" at -15.846,17.917 h1.2
  text "钻直径0.5mm的NPTH清角孔" at -13.56,15.631 h1.2
  text "33.80mm" at 66.352,0.025 h0.5
  text "SLOT" at 74.586,-3.441 h0.6 r90
  text "50.00mm" at 46.37,-3.905 h0.5
  text "SLOT" at 74.4,-15.4 h0.45 r90
  text "116.00mm" at 20.336,-21.675 h0.5
  text "1" at 21.523,-23.233 h0.75
Mechanical2:
  lines w0.1: -30.519,14.8 27.875,14.8 ; -29.129,-16 25.642,-16 ; 22.093,-17.8 22.093,12.6
  text "FR-4  4L 2.0MM 2OZ 绿油白字" at -48.999,-38.937 h1.5
  text "AC:3000V / 0.3mA" at -48.899,-41.407 h1.5
  text "DC:500V / 100MΩ (min)" at -48.909,-43.697 h1.5
Mechanical3:
  lines w0.254: -144.111,-22.109 -141.611,-22.109 ; -144.111,47.891 -141.611,47.891 ; -144.111,117.891 -141.611,117.891 ; -141.615,146.123 -141.611,185.391 -132.935,185.391 ; -141.611,-65.097 253.389,-65.097 253.389,185.391 -133.111,185.391 ; -141.611,-65.091 -141.611,85.161 -141.611,146.091 ; -77.445,-92.109 -77.444,-89.657 ; -77.444,185.401 -77.444,187.891 ; -12.105,-92.109 -12.105,-89.657 ; -10.778,187.831 -10.775,185.391 ; 55.895,-92.109 55.895,-89.657 ; 107.681,-89.657 3.901,-89.657 -135.113,-89.657 -135.113,-66.136 3.901,-66.136 107.735,-66.117 107.738,-89.638 ; 107.725,-92.077 107.729,-89.689 ; 109.915,-71.171 109.915,-66.167 ; 109.915,-71.157 140.895,-71.157 ; 109.934,-66.156 140.985,-66.156 ; 109.945,-82.157 140.915,-82.158 ; 109.945,-82.117 109.935,-77.177 141.005,-77.177 ; 122.556,185.401 122.556,187.881 ; 124.953,-89.659 124.953,-82.897 109.953,-82.897 109.953,-89.654 124.953,-89.654 ; 131.355,-71.703 131.355,-76.657 137.885,-76.657 ; 131.355,-71.658 137.875,-71.658 ; 137.855,-76.657 148.854,-76.657 ; 137.857,-71.658 148.855,-71.658 148.855,-76.662 ; 140.553,-89.659 140.553,-82.897 125.553,-82.897 125.553,-89.654 140.553,-89.654 ; 140.885,-82.158 202.887,-82.158 202.887,-77.18 140.885,-77.18 ; 140.885,-71.16 202.887,-71.16 202.887,-66.156 140.885,-66.156 ; 156.153,-89.659 156.153,-82.897 141.153,-82.897 141.153,-89.654 156.153,-89.654 ; 171.753,-89.659 171.753,-82.897 156.753,-82.897 156.753,-89.654 171.753,-89.654 ; 178.845,-76.637 189.255,-76.647 202.895,-76.647 202.887,-71.668 198.899,-71.668 194.886,-71.668 190.898,-71.668 ; 178.846,-76.672 178.846,-71.668 190.935,-71.668 ; 185.289,-92.092 185.289,-89.662 ; 187.353,-89.665 187.353,-82.903 172.353,-82.903 172.353,-89.659 187.353,-89.659 ; 189.222,185.391 189.222,187.871 ; 253.449,117.893 255.879,117.891 ; 253.489,-22.107 255.879,-22.109 ; 253.509,47.893 255.889,47.893 ; 203.877,-72.659 203.877,-66.156 ; 203.877,-72.659 203.877,-66.156 ; 203.877,-72.659 253.389,-72.659 253.389,-66.156 203.877,-66.156 ; -144.111,-92.109 255.889,-92.109 255.889,187.891 -144.111,187.891 -144.111,-92.109 ; -141.615,-89.667 -141.615,-66.146 -136.122,-66.146 -136.122,-89.667 -141.615,-89.667 ; 55.889,185.391 55.889,187.891 55.889,185.391 ; 109.915,-76.637 109.925,-71.668 130.365,-71.657 130.365,-76.637 109.915,-76.637 ; 149.655,-76.672 149.655,-71.668 177.9,-71.668 177.9,-76.672 149.655,-76.672 ; 187.953,-89.665 202.953,-89.665 202.953,-82.909 187.953,-82.909 187.953,-89.665 ; 203.877,-89.665 203.877,-73.675 253.389,-73.675 253.389,-89.665 203.877,-89.665 ; 253.389,-66.357 253.389,-66.357
  text "1" at -110.791,185.781 h1.8
  text "3" at 22.549,185.751 h1.8
  text "4" at 89.219,185.761 h1.8
  text "5" at 155.869,185.731 h1.8
  text "6" at 222.579,185.741 h1.8
  text "2" at -44.141,185.721 h1.8
  text "D" at -143.591,152.891 h2
  text "D" at 254.009,152.883 h2
  text "C" at -143.641,82.891 h2
  text "C" at 253.889,82.873 h2
  text "B" at -143.501,12.891 h2
  text "B" at 253.919,12.883 h2
  text "A" at -143.621,-57.109 h2
  text "GREAT WALL POWER SUPPLY TECHNOLOGY CO.,LTD." at 113.535,-69.257 h1.8
  text "P/N :" at 207.502,-70.749 h2.6
  text "mm" at 122.425,-74.917 h1.8
  text "SIZE  A3" at 134.505,-75.027 h1.8
  text "SHEET 1 OF 2" at 152.722,-75.149 h2
  text "V02" at 189.009,-75.179 h1.8
  text "UNIT" at 112.265,-75.217 h1.8
  text "TOLERANCE" at 114.035,-79.257 h1.4
  text "TITLE" at 207.412,-79.619 h3
  text "+/-0.15mm" at 158.525,-80.677 h2
  text "UNLESS OTHERWISE SPECIFIED" at 113.435,-81.387 h1.4
  text "ISSUE" at -137.211,-84.079 h3.2 r90
  text "APPROVED" at 175.739,-84.879 h1.2
  text "DATE" at 193.442,-84.904 h1.2
  text "CHECKED" at 129.13,-84.98 h1.2
  text "CHECKED" at 144.598,-84.98 h1.2
  text "DESIGNED" at 112.853,-84.997 h1.2
  text "AUDIT" at 161.464,-85.209 h1.2
  text "CRPS-T-SB-10W" at 207.674,-86.731 h3
  text "HeYaQin" at 130.589,-87.809 h2
  text "Qinchunyan" at 174.545,-87.977 h2
  text "2024.08.30" at 191.283,-87.977 h1.2
  text "YangPing" at 112.053,-87.997 h2
  text "Wangjing" at 160.803,-88.054 h2
  text "WangWenYong" at 142.523,-88.128 h2
  text "1" at -110.791,-91.769 h1.8
  text "2" at -44.141,-91.769 h1.8
  text "4" at 89.219,-91.769 h1.8
  text "5" at 155.869,-91.809 h1.8
  text "6" at 222.579,-91.879 h1.8
  text "3" at 22.559,-91.909 h1.8
Mechanical4:
  lines w0.254: -144.111,47.893 -141.731,47.893 ; -144.101,-22.109 -141.711,-22.107 ; -144.101,117.891 -141.671,117.893 ; -79.157,-71.668 -67.068,-71.668 -67.068,-76.672 ; -79.12,-71.668 -83.108,-71.668 -87.121,-71.668 -91.109,-71.668 -91.117,-76.647 -77.477,-76.647 -67.067,-76.637 ; -77.444,185.391 -77.444,187.871 ; -75.575,-89.665 -75.575,-82.903 -60.575,-82.903 -60.575,-89.659 -75.575,-89.659 ; -73.511,-92.092 -73.511,-89.662 ; -59.975,-89.659 -59.975,-82.897 -44.975,-82.897 -44.975,-89.654 -59.975,-89.654 ; -44.375,-89.659 -44.375,-82.897 -29.375,-82.897 -29.375,-89.654 -44.375,-89.654 ; -37.077,-76.662 -37.077,-71.658 -26.079,-71.658 ; -37.076,-76.657 -26.077,-76.657 ; -29.227,-77.177 1.843,-77.177 1.833,-82.117 ; -29.207,-66.156 1.844,-66.156 ; -29.137,-82.158 1.833,-82.157 ; -29.117,-71.157 1.863,-71.157 ; -29.107,-82.158 -91.109,-82.158 -91.109,-77.18 -29.107,-77.18 ; -29.107,-71.16 -91.109,-71.16 -91.109,-66.156 -29.107,-66.156 ; -28.775,-89.659 -28.775,-82.897 -13.775,-82.897 -13.775,-89.654 -28.775,-89.654 ; -26.107,-76.657 -19.577,-76.657 -19.577,-71.703 ; -26.097,-71.658 -19.577,-71.658 ; -13.175,-89.659 -13.175,-82.897 1.825,-82.897 1.825,-89.654 -13.175,-89.654 ; -10.778,185.401 -10.778,187.881 ; 1.863,-71.171 1.863,-66.167 ; 4.04,-89.638 4.043,-66.117 107.877,-66.136 246.891,-66.136 246.891,-89.657 107.877,-89.657 4.097,-89.657 ; 4.049,-89.689 4.053,-92.077 ; 55.883,-92.109 55.883,-89.657 ; 122.553,185.391 122.556,187.831 ; 123.883,-92.109 123.882,-89.657 ; 189.223,-92.109 189.222,-89.657 ; 189.222,185.401 189.222,187.891 ; 244.713,185.391 253.389,185.391 253.393,146.123 ; 244.889,185.391 -141.611,185.391 -141.611,-65.097 253.389,-65.097 ; 253.389,-65.091 253.389,85.161 253.389,146.091 ; 253.389,-22.109 255.889,-22.109 ; 253.389,47.891 255.889,47.891 ; 253.389,117.891 255.889,117.891 ; -92.099,-72.659 -141.611,-72.659 -141.611,-66.156 -92.099,-66.156 ; -92.099,-72.659 -92.099,-66.156 ; -92.099,-72.659 -92.099,-66.156 ; -144.111,-92.109 -144.111,187.891 255.889,187.891 255.889,-92.109 -144.111,-92.109 ; -141.611,-89.665 -92.099,-89.665 -92.099,-73.675 -141.611,-73.675 -141.611,-89.665 ; -141.611,-66.357 -141.611,-66.357 ; -91.175,-89.665 -91.175,-82.909 -76.175,-82.909 -76.175,-89.665 -91.175,-89.665 ; -66.122,-76.672 -37.877,-76.672 -37.877,-71.668 -66.122,-71.668 -66.122,-76.672 ; -18.587,-76.637 1.863,-76.637 1.853,-71.668 -18.587,-71.657 -18.587,-76.637 ; 55.889,185.391 55.889,187.891 55.889,185.391 ; 247.9,-89.667 253.392,-89.667 253.392,-66.146 247.9,-66.146 247.9,-89.667
  text "1" at 222.569,185.781 h1.8
  text "4" at 22.559,185.761 h1.8
  text "3" at 89.229,185.751 h1.8
  text "6" at -110.801,185.741 h1.8
  text "5" at -44.091,185.731 h1.8
  text "2" at 155.919,185.721 h1.8
  text "D" at -142.231,152.883 h2
  text "D" at 255.369,152.891 h2
  text "C" at 255.419,82.891 h2
  text "C" at -142.111,82.873 h2
  text "B" at -142.141,12.883 h2
  text "B" at 255.279,12.891 h2
  text "A" at 255.399,-57.109 h2
  text "GREAT WALL POWER SUPPLY TECHNOLOGY CO.,LTD." at -1.757,-69.257 h1.8
  text "P/N :" at -95.725,-70.749 h2.6
  text "mm" at -10.647,-74.917 h1.8
  text "SIZE  A3" at -22.727,-75.027 h1.8
  text "SHEET 1 OF 2" at -40.945,-75.149 h2
  text "V02" at -77.231,-75.179 h1.8
  text "UNIT" at -0.487,-75.217 h1.8
  text "TOLERANCE" at -2.257,-79.257 h1.4
  text "TITLE" at -95.635,-79.619 h3
  text "+/-0.15mm" at -46.747,-80.677 h2
  text "UNLESS OTHERWISE SPECIFIED" at -1.657,-81.387 h1.4
  text "ISSUE" at 248.989,-84.079 h3.2 r270
  text "APPROVED" at -63.961,-84.879 h1.2
  text "DATE" at -81.664,-84.904 h1.2
  text "CHECKED" at -32.82,-84.98 h1.2
  text "CHECKED" at -17.352,-84.98 h1.2
  text "DESIGNED" at -1.075,-84.997 h1.2
  text "AUDIT" at -49.686,-85.209 h1.2
  text "CRPS-T-SB-10W" at -100.811,-85.909 h3
  text "2024.08.30" at -79.505,-87.977 h1.2
  text "Qinchunyan" at -62.767,-87.977 h2
  text "YangPing" at -0.275,-87.997 h2
  text "Wangjing" at -49.025,-88.054 h2
  text "WangWenYong" at -30.578,-88.128 h2
  text "HeYaQin" at -18.411,-88.209 h2
  text "4" at 22.559,-91.769 h1.8
  text "2" at 155.919,-91.769 h1.8
  text "1" at 222.569,-91.769 h1.8
  text "5" at -44.091,-91.809 h1.8
  text "6" at -110.801,-91.879 h1.8
  text "3" at 89.219,-91.909 h1.8
Mechanical7:
  circle w0.02: c-24.013,-1.252 r1.35
  circle w0.02: c-22.313,-5.352 r1.35
  lines w0.01: -28.8,-15.5 ccw(c-27.8,-15.5) -27.8,-16.5 17.2,-16.5 ccw(c17.2,-15.5) 18.2,-15.5 18.2,-13 21.2,-13 21.2,13.5 20.7,14 20.7,17.3 9.2,17.3 9.2,14.5 -16.8,14.5 -16.8,17.3 -28.1,17.3 -28.1,13.7 -28.8,13 -28.8,-15.5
